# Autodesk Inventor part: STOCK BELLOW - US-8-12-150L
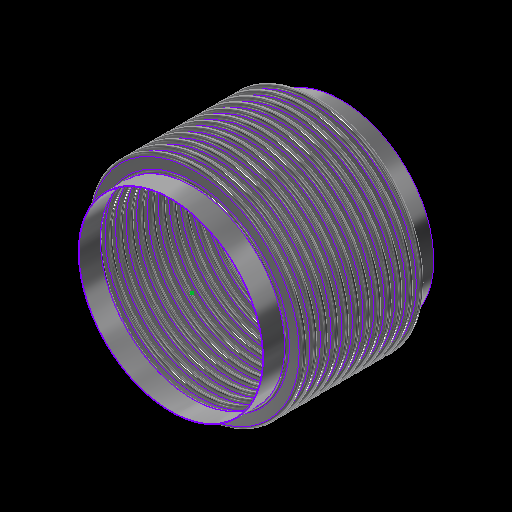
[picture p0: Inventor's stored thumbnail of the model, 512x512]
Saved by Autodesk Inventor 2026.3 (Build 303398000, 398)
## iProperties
Category: 20 GA (0.036 THICK)
RuleStatus: InUse
Created: 2024-01
Part Number: STOCK BELLOW - US-8-12-150L
Project: =STOCK BELLOWS: <Stock Number><SFILL>
Material: ASTM A240-304
Description: =STOCK BELLOWS: <Stock Number>, <SID_> I.D., <SOD_> O.D., <SPLY_> PLY, <Category>, <SNET_CONS> CONS.<PITCH_><STANGENT_> TANGENT<SFILL>
Document SubType Name: Sheet Metal
Designer: GS
Stock Number: U.S-8-12-150L
Surface Area: 8553.82 cm^2
Volume: 389.347 cm^3
Sheet Metal Rule: Default
Appearance: STAINLESS STEEL
Mass: 3137.08 g
Density: 8.05729 g/cm^3
THK: 0.036
ID: 3.500
OD: 4.250
CONS_: 2
PITCH: 0.500
TANGENT: 0.500
BELLOWS_UPSET: 0.000
d79: 1.000
d82: 1.000
d83: 26.000
d84: 24.000
d174: 8
d214: 8
STHK_: 0.036
SID_: 8.625
SOD_: 10.125
SPITCH_: 0.500
STANGENT__: 1.000
SBELLOWS_UPSET_: 0.000
SDIFF_TAN: 1.000
d252: 2
d275: 2
d287: 0.050
d289: 0.500
d290: 0.000
SOD_NECK: 8 11/16
PLY: 1
PSET: 4.178
PBAR: 1.035
COUNTER: 1.500
NET_TUBE: 3.071
CONS: 2
S_CONS: 0
NET_CONS: 2
ID_M: 88.90 mm
OD_M: 107.95 mm
THK_M: 0.91 mm
ID_U: 3.500 in
OD_U: 4.250 in
THK_U: 0.036 in
TANGENT2: 0.500
TAN_TO_TAN: 1.000 in
d80: 2.571
d81: 10
SID: 2.375
SCONS_: 12
SPITCH: 0.250
STANGENT_: 1.000
SBELLOWS_UPSET: 0.000
SNET_CONS: 12
SS_CONS: 0
SCONS: 8
d190: 8
d191: 1
d192: 1
d193: 8
d194: 0
SIZE: 8.00
PRESSURE: 150
d230: 8
STANGENT: 4.000
SPLY_: 1
d233: 8
d234: 0
d263: 2
d265: 1
d268: 2
d269: 0
d286: 2
d288: 1
d291: 2
d292: 0
SREROLL: 0.750
BLETP: 1.000 ul
PRES_Copy: 85
MATTABLE: 20 GA (0.036 THICK)
PART_NUMBER: U.S-8-12-150L
PITCH_: =, <SPITCH_> PITCH,
CFILL: .
SFILL: .
MESH: ,
COMP: 1.22
EXT: 0.61
LAT: 0.26
ANG: 573
ASR: 1601
LSR: 5276
ANSR: 276
PRES: 150
COMPM: 12.2
EXTM: 6.1
LATM: 2.60
ASRM: 280.383
PRESM: 10.342
LSRM: 923.986
ANSRM: 48.336
TEMPMIN: 20
TEMPMAX: 800
TEMPMINM: -7
TEMPMAXM: 427
WEIGHTM: 3.137
WEIGHT: 6.916
Author: GS
Keywords: 20 GA (0.036 THICK)
Comments: =STOCK BELLOW - <STOCK NUMBER>
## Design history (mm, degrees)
sketch "Sketch2"
  geometry: L1 (0, -177.245)-(0, 562.856) reference; L2 (45.364, 0)-(44.45, 0); L3 (48.082, -2.718)-(50.343, -2.718); L4 (48.082, -3.632)-(50.343, -3.632); L5 (50.343, -9.982)-(48.082, -9.982); L6 (50.343, -9.068)-(48.082, -9.068); L7 (45.364, -12.7)-(44.45, -12.7); L8 (48.082, 0)-(48.082, -12.7); L9 (50.343, -6.35)-(53.975, -6.35); L10 (44.45, 0)-(44.45, -12.7); L11 (20.376, 102.841)-(20.376, 101.926); L12 (58.262, 457.127)-(58.262, 349.177); L13 (58.262, 444.427)-(58.262, 336.477); L14 (93.133, -58.817)-(93.133, -71.517); L15 (118.746, -66.401)-(118.746, -66.401); L16 (50.343, -9.068)-(50.343, -9.982); L17 (48.082, -9.068)-(48.082, -9.982); L18 (48.082, -9.525)-(50.343, -9.525); L19 (53.975, 0)-(53.975, -12.7); L20 (-50.343, -9.068)-(-50.343, -9.982); L21 (-50.343, -2.718)-(-48.082, -2.718); L22 (-50.343, -3.632)-(-48.082, -3.632); L23 (-48.082, -9.068)-(-50.343, -9.068); L24 (-50.343, -9.525)-(-48.082, -9.525); L25 (-48.082, -9.982)-(-50.343, -9.982); L26 (-48.082, -9.068)-(-48.082, -9.982); L27 (-44.45, 0.653)-(-44.45, -12.047); L28 (-48.082, -6.35)-(-44.45, -6.35); L29 (-50.343, 0.653)-(-50.343, -12.7); L30 (-53.061, 0)-(-53.975, 0); L31 (-53.975, 0)-(-53.975, -12.7); L32 (-53.061, -12.7)-(-53.975, -12.7); A1 r 2.718 centre (48.082, 0) between (45.364, 0) and (48.082, -2.718); A2 r 3.632 centre (48.082, 0) between (44.45, 0) and (48.082, -3.632); A3 r 3.632 centre (50.343, -6.35) between (50.343, -9.982) and (50.343, -2.718); A4 r 2.718 centre (50.343, -6.35) between (50.343, -9.068) and (50.343, -3.632); A5 r 2.718 centre (48.082, -12.7) between (48.082, -9.982) and (45.364, -12.7); A6 r 3.632 centre (48.082, -12.7) between (48.082, -9.068) and (44.45, -12.7); A7 r 3.175 centre (50.343, -6.35) between (50.343, -9.525) and (53.518, -6.35); A8 r 3.175 centre (48.082, -12.7) between (48.082, -9.525) and (44.907, -12.7); A9 r 2.718 centre (-50.343, -12.7) between (-50.343, -9.982) and (-53.061, -12.7); A10 r 2.718 centre (-48.082, -6.35) between (-48.082, -9.068) and (-48.082, -3.632); A11 r 3.175 centre (-48.082, -6.35) between (-48.082, -9.525) and (-44.907, -6.35); A12 r 3.632 centre (-48.082, -6.35) between (-48.082, -9.982) and (-48.082, -2.718); A13 r 3.175 centre (-50.343, -12.7) between (-50.343, -9.525) and (-53.518, -12.7); A14 r 3.632 centre (-50.343, -12.7) between (-50.343, -9.068) and (-53.975, -12.7); A15 r 2.718 centre (-50.343, 0) between (-53.061, 0) and (-50.343, -2.718); A16 r 3.632 centre (-50.343, 0) between (-53.975, 0) and (-50.343, -3.632); 10 further points
  constraints: 62 end point, 38 point on circle, 20 tangent, 16 centre point, 12 parallel, 9 midpoint, 7 vertical, 6 coincident, 6 concentric, 6 point on line, 4 equal radius, 4 perpendicular, 3 horizontal, 1 collinear, 1 horizontal alignment, 10 other
  dimensions: "THK" = 0.9144 distance of L11.start L11.end; "ID" = 88.9 distance of L11.end point (20.376, 13.026); "OD" = 107.95 distance of L12.start L12.end; "PITCH" = 12.7 distance of L12.start L13.start; "TANGENT" = 12.7 distance of L14.start L14.end; "BELLOWS_UPSET" = 0 distance of L15.start L15.end; "d43" = 88.9 diameter of L10 L1 (= ID); "d44" = 107.95 diameter of L9.end L1 (= OD); "d45" = 0.9144 distance between parallel lines of L5 L6 (computed from THK, PLY); "d46" = 3.6322 radius of A3 (computed from PITCH, THK, PLY); "UPSET_PITCH" = 12.7 distance of L2.end L7.end (derived); "SIDEWALL_ANGLE" = 360 deg dimension on L3 L9 (derived); "CON_GAP" = 5.4356 distance of point (48.082, -9.068) point (48.082, -3.632) (derived); "TAN1" = 4.98728 dimension on A8 (derived); "TAN2" = 4.98728 dimension on A7 (derived); "LEG1" = 2.2606 distance of L18.start L18.end (derived); "d278" = 0.9144 distance between parallel lines of L25 L23 (derived); "d279" = 3.6322 radius of A12 (derived); "d280" = 12.7 distance of L30.end L31.end (derived); "d281" = 360 deg dimension on L21 L28 (derived); "d282" = 5.4356 distance of point (-50.343, -9.068) point (-50.343, -3.632) (derived); "d283" = 4.98728 dimension on A13 (derived); "d284" = 4.98728 dimension on A11 (derived); "d285" = 2.2606 distance of L24.start L24.end (derived); "d293" = 88.9 diameter of L27 L1 (derived); "d294" = 107.95 diameter of L31 L1 (derived)
  node "Sketch Rectangular Pattern1" dims "d31" = 25.4, "ID" = 88.9
  node "Sketch Rectangular Pattern2" dims "d39" = 25.4, "PITCH" = 12.7
revolve "CONS" stored, may be unused: angle "d48" = 90 deg
node "BELLOW MIDPLANE"
pattern_linear "Rectangular Pattern2" dims "d52" = 12.7 (= UPSET_PITCH)
sketch "Sketch5"
  geometry: C1 r 45.364 at (0, 0) reference; C2 r 44.45 at (0, 0) reference
extrude "TANGENT" new body sketch "Sketch5" distance "d53" = 12.7 (= TANGENT); taper "d54" = 0 deg
revolve "SAMETAN" stored, may be unused: angle "d65" = 90 deg
revolve "DIFFTAN" stored, may be unused: angle "d70" = 90 deg
sketch "Sketch9"
  geometry: L1 (53.319, 0)-(-53.319, 0) reference; L2 (0, -17.78)-(0, 17.78) reference; L3 (38.085, 0)-(-38.085, 0); L4 (38.085, -11.906)-(38.085, 11.906); L5 (25.385, -11.906)-(25.385, 11.906); L6 (13.15, 11.906)-(13.15, -11.906); L7 (-25.385, -11.906)-(-25.385, 11.906); L8 (-38.085, -11.906)-(-38.085, 11.906); L9 (37.291, -11.906)-(37.291, 11.906); L10 (38.085, -11.906)-(37.291, -11.906); L11 (38.085, 11.906)-(37.291, 11.906); L12 (13.546, 11.906)-(12.753, 11.906); L13 (12.753, 11.906)-(12.753, -11.906); L14 (12.753, -11.906)-(13.546, -11.906); L15 (13.546, -11.906)-(13.546, 11.906); L16 (-13.546, 11.906)-(-13.546, -11.906); L17 (-13.15, 11.906)-(-13.15, -11.906); L18 (-13.546, -11.906)-(-12.753, -11.906); L19 (-12.753, -11.906)-(-12.753, 11.906); L20 (-12.753, 11.906)-(-13.546, 11.906); L21 (-38.085, -11.906)-(-37.291, -11.906); L22 (-37.291, -11.906)-(-37.291, 11.906); L23 (-37.291, 11.906)-(-38.085, 11.906); L24 (-38.085, 11.906)-(-38.085, -11.906); L25 (38.085, -0.397)-(-38.085, -0.397); L26 (-38.085, -0.397)-(-38.085, 0.397); L27 (-38.085, 0.397)-(38.085, 0.397); L28 (38.085, 0.397)-(38.085, -0.397); L29 (-38.085, 11.906)-(38.085, 11.906); L30 (38.085, 11.906)-(38.085, 12.7); L31 (38.085, 12.7)-(-38.085, 12.7); L32 (-38.085, 12.7)-(-38.085, 11.906); L33 (38.085, -11.906)-(-38.085, -11.906); L34 (-38.085, -11.906)-(-38.085, -12.7); L35 (-38.085, -12.7)-(38.085, -12.7); L36 (38.085, -12.7)-(38.085, -11.906); 30 further points
  constraints: 68 end point, 13 midpoint, 13 parallel, 8 horizontal, 7 perpendicular, 6 equal length, 3 point on line, 2 vertical, 14 other
  dimensions: "d115" = 23.8125 distance of L4.start L4.end (derived); "d116" = 12.7 distance between parallel lines of L4 L5 (derived); "d117" = 12.23516 distance between parallel lines of L5 L6 (derived); "d125" = 38.53427 distance between parallel lines of L7 L6 (derived); "d127" = 12.7 distance between parallel lines of L8 L7 (derived); "d128" = 24.93516 distance between parallel lines of L6 L4 (derived); "d130" = 76.16943 distance between parallel lines of L8 L4 (derived); "RULER_THK" = 0.79375 distance between parallel lines of L4 L9; "d135" = 0.79375 distance of L13.end L14.end (derived); "d138" = 26.29911 distance of L13.end L16.end (derived); "d143" = 0.79375 distance of L22.end L8.end (derived); "d144" = 0.79375 distance between parallel lines of L27 L25 (derived)
extrude "RULER" join sketch "Sketch9" distance "d149" = 0.79375 (derived); taper "d150" = 0 deg
extrude "BARS" join sketch "Sketch9" distance "d151" = 0.79375 (derived); taper "d152" = 0 deg
pattern_linear "Rectangular Pattern4" dims "d155" = 26.29911 (derived)
sketch "Sketch13"
  geometry: L1 (93.149, -52.467)-(93.149, -77.867); L2 (110.452, 0)-(109.537, 0); L3 (110.452, -12.7)-(109.537, -12.7); L4 (124.955, -9.982)-(113.17, -9.982); L5 (124.955, -9.068)-(113.17, -9.068); L6 (124.955, -6.35)-(128.588, -6.35); L7 (113.17, -2.718)-(124.955, -2.718); L8 (113.17, 0)-(113.17, -12.7); L9 (109.537, 0)-(109.537, -12.7); L10 (58.254, -239.256)-(58.254, -496.431); L11 (58.254, -251.956)-(58.254, -509.131); L12 (58.254, -277.356)-(58.254, -534.531); L13 (58.254, -290.056)-(58.254, -547.231); L14 (58.254, -302.756)-(58.254, -559.931); L15 (58.254, -315.456)-(58.254, -572.631); L16 (58.254, -328.156)-(58.254, -585.331); L17 (58.254, -264.656)-(58.254, -521.831); L18 (20.376, 102.841)-(20.376, 101.926); L19 (113.17, -3.632)-(124.955, -3.632); L20 (0, -722.965)-(0, 240.475) reference; L21 (-25.718, 0)-(154.305, 0) reference; A1 r 2.718 centre (113.17, 0) between (110.452, 0) and (113.17, -2.718); A2 r 2.718 centre (113.17, -12.7) between (113.17, -9.982) and (110.452, -12.7); A3 r 3.632 centre (113.17, -12.7) between (113.17, -9.068) and (109.537, -12.7); A4 r 2.718 centre (124.955, -6.35) between (124.955, -9.068) and (124.955, -3.632); A5 r 3.632 centre (124.955, -6.35) between (124.955, -9.982) and (124.955, -2.718); A6 r 3.632 centre (113.17, 0) between (109.537, 0) and (113.17, -3.632); 6 further points; 1 other entity
  constraints: 38 end point, 15 point on circle, 9 tangent, 6 centre point, 6 parallel, 5 vertical alignment, 4 point on line, 4 vertical, 3 coincident, 3 concentric, 2 collinear, 2 equal radius, 1 horizontal, 1 perpendicular, 23 other
  dimensions: "SBELLOWS_UPSET_" = 0 distance of point (118.762, -66.401) point (118.762, -66.401); "STOTAL_THK_BELLOW__" = 0.9144 distance between parallel lines of L4 L5 (derived); "d224" = 3.6322 radius of A5 (derived); "d225" = 12.7 distance of L2.end L3.end (derived); "SSIDEWALL_ANGLE_" = 360 deg dimension on L7 L6 (derived); "SSCON_GAP_" = 5.4356 distance of point (113.17, -9.068) point (113.17, -3.632) (derived); "d235" = 219.075 diameter of L9 L20 (derived); "d236" = 257.175 diameter of L6.end L20 (derived)
  node "Sketch Rectangular Pattern4" dims "d228" = 25.4
  node "Sketch Rectangular Pattern5" dims "d229" = 25.4
revolve "SBELLOW" stored, may be unused: angle "d197" = 90 deg
pattern_linear "Rectangular Pattern5" dims "d204" = 12.7 (derived)
revolve "STANGENT" stored, may be unused: angle "d240" = 90 deg
revolve "SSAMETAN" stored, may be unused: angle "d241" = 90 deg
revolve "SDIFFTAN" stored, may be unused: angle "d246" = 90 deg
revolve "INVCON" stored, may be unused: angle "d295" = 90 deg
pattern_linear "Rectangular Pattern6" dims "d298" = 12.7 (derived)
revolve "INVTANGENT" stored, may be unused: angle "d302" = 90 deg
revolve "INVSAMETAN" stored, may be unused: angle "d307" = 90 deg
revolve "INVDIFFTAN" stored, may be unused: angle "d312" = 90 deg
sketch "ID BELLOW MOUNT CALC"
  geometry: L1 (44.45, 0)-(38.1, 0); L2 (38.1, 0)-(38.1, 12.7); L3 (38.1, 12.7)-(44.45, 12.7); L4 (44.45, 12.7)-(44.45, 0); L5 (36.513, 12.7)-(35.598, 12.7); L6 (35.598, 12.7)-(35.598, 0); L7 (35.598, 0)-(36.513, 0); L8 (36.513, 0)-(36.513, 12.7); L9 (0, -2.54)-(0, 15.24) reference; L10 (-8.89, 0)-(53.34, 0) reference; 1 further point
  constraints: 16 end point, 5 parallel, 2 collinear, 2 horizontal, 2 perpendicular
  dimensions: "d314" = 12.7 distance of L5.end L6.end (derived); "d315" = 0.9144 distance of L5.start L5.end (derived); "IG" = 1.5875 distance between parallel lines of L2 L8; "PIPE_OD" = 88.9 diameter of L4 L9; "PIPE_WALL" = 6.35 distance of L2.end L3.end; "ID_MT_BELLOW" = 71.1962 diameter of L6 L9 (derived)
revolve "CFILL" stored, may be unused: angle "d320" = 90 deg
pattern_linear "Rectangular Pattern7" dims "d323" = 12.7 (derived)
revolve "SFILL" stored, may be unused: angle "d324" = 90 deg
pattern_linear "Rectangular Pattern8" dims "d327" = 12.7 (derived)
node "STOCK BELLOW MIDPLANE"
node "BELLOW"
sketch "Sketch6"
  geometry: L1 (-12.7, 45.364)-(0, 45.364); L2 (0, 45.364)-(0, 44.45); L3 (0, 44.45)-(-12.7, 44.45); L4 (-12.7, 44.45)-(-12.7, 45.364); L5 (10.16, 0)-(-60.96, 0) reference; L6 (-38.1, -89.422)-(-38.1, 153.44) reference; 1 further point
  constraints: 8 end point, 2 parallel, 1 horizontal, 1 perpendicular
  dimensions: "d61" = 12.7 distance of L2.end L3.end (derived); "d62" = 0.9144 distance of L1.end L2.end (derived); "d63" = 88.9 diameter of L3 L5 (derived); "d64" = 25.4 distance between parallel lines of L4 L6 (derived)
sketch "Sketch12"
  geometry: 1 further point
sketch "Sketch14"
  geometry: L1 (-25.4, 110.452)-(0, 110.452); L2 (0, 110.452)-(0, 109.537); L3 (0, 109.537)-(-25.4, 109.537); L4 (-25.4, 109.537)-(-25.4, 110.452); L5 (5.08, 0)-(-30.48, 0) reference; L6 (0, -22.09)-(0, 132.542) reference; 1 further point
  constraints: 8 end point, 2 parallel, 1 collinear, 1 horizontal, 1 perpendicular
  dimensions: "d237" = 0.9144 distance of L3.end L1.start (derived); "d238" = 219.075 diameter of L3 L5 (derived); "d239" = 25.4 distance of L1.start L1.end (derived); "SOD_NECK" = 220.9038 diameter of L1 L5 (derived)
sketch "Sketch15"
  geometry: L1 (-22.09, 0)-(132.542, 0) reference; L2 (109.538, -152.4)-(110.452, -152.4); L3 (110.452, -152.4)-(110.452, -177.8); L4 (110.452, -177.8)-(109.538, -177.8); L5 (109.538, -177.8)-(109.538, -152.4); L6 (0, -215.9)-(0, 50.8) reference; 1 further point
  constraints: 8 end point, 2 parallel, 1 horizontal, 1 perpendicular
  dimensions: "d205" = 25.4 distance of L4.end L2.start (derived); "d206" = 0.9144 distance of L3.end L4.end (derived); "d207" = 219.075 diameter of L5 L6 (derived); "d208" = 152.4 distance between parallel lines of L1 L2 (derived)
node "TANGENT_"
node "SAME_TAN"
sketch "Sketch8"
  geometry: L1 (45.364, -25.4)-(44.45, -25.4); L2 (44.45, -25.4)-(44.45, -38.1); L3 (44.45, -38.1)-(45.364, -38.1); L4 (45.364, -38.1)-(45.364, -25.4); L5 (0, -48.26)-(0, 22.86) reference; L6 (-89.422, 0)-(153.44, 0) reference; 1 further point
  constraints: 8 end point, 2 parallel, 1 horizontal, 1 perpendicular
  dimensions: "d66" = 88.9 diameter of L2 L5 (derived); "TOTAL_THK_BELLOW" = 0.9144 distance of L2.end L3.end (derived); "d68" = 25.4 distance between parallel lines of L1 L6 (derived); "d69" = 12.7 distance of L1.end L2.end (derived)
node "DIFF_TAN"
node "Sketch Rectangular Pattern3" dims "d138" = 26.29911 (derived), "d141" = 25.4
node "SBELLOW_"
node "STANGENT_"
node "SSAME_TAN"
sketch "Sketch16"
  geometry: L1 (110.452, -152.4)-(109.538, -152.4); L2 (109.538, -152.4)-(109.538, -177.8); L3 (109.538, -177.8)-(110.452, -177.8); L4 (110.452, -177.8)-(110.452, -152.4); L5 (0, -215.9)-(0, 50.8) reference; L6 (-22.09, 0)-(132.542, 0) reference; 1 further point
  constraints: 8 end point, 2 parallel, 1 horizontal, 1 perpendicular
  dimensions: "SDIFF_TAN" = 25.4 distance of L3.end L1.start; "d243" = 0.9144 distance of L2.end L3.end (derived); "d244" = 152.4 distance between parallel lines of L1 L6 (derived); "d245" = 219.075 diameter of L2 L5 (derived)
node "SDIFF_TAN"
body "Solid15"
sketch "Sketch17"
  geometry: L1 (53.975, 12.7)-(53.061, 12.7); L2 (53.061, 12.7)-(53.061, 0); L3 (53.061, 0)-(53.975, 0); L4 (53.975, 0)-(53.975, 12.7); L5 (0, -2.54)-(0, 15.24) reference; L6 (-10.795, 0)-(64.77, 0) reference; 2 further points
  constraints: 8 end point, 2 parallel, 1 horizontal, 1 midpoint, 1 perpendicular, 1 point on line
  dimensions: "INVTANGENT" = 12.7 distance of L3.end L1.start (derived); "d300" = 0.9144 distance of L1.start L1.end (derived); "d301" = 107.95 diameter of L4 L5 (derived)
body "Solid16"
sketch "Sketch18"
  geometry: L1 (53.975, -25.4)-(53.061, -25.4); L2 (53.061, -25.4)-(53.061, -38.1); L3 (53.061, -38.1)-(53.975, -38.1); L4 (53.975, -38.1)-(53.975, -25.4); L5 (-10.795, 0)-(64.77, 0) reference; L6 (0, -48.26)-(0, 22.86) reference; 1 further point
  constraints: 8 end point, 2 parallel, 1 horizontal, 1 perpendicular
  dimensions: "d303" = 25.4 distance between parallel lines of L1 L5 (derived); "d304" = 12.7 distance of L3.end L1.start (derived); "d305" = 0.9144 distance of L2.end L3.end (derived); "d306" = 107.95 diameter of L4 L6 (derived)
body "Solid17"
sketch "Sketch19"
  geometry: L1 (53.975, -25.4)-(53.061, -25.4); L2 (53.061, -25.4)-(53.061, -38.1); L3 (53.061, -38.1)-(53.975, -38.1); L4 (53.975, -38.1)-(53.975, -25.4); L5 (0, -48.26)-(0, 22.86) reference; L6 (-10.795, 0)-(64.77, 0) reference; 1 further point
  constraints: 8 end point, 2 parallel, 1 horizontal, 1 perpendicular
  dimensions: "d308" = 12.7 distance of L1.end L2.end (derived); "d309" = 107.95 diameter of L4 L5 (derived); "d310" = 0.9144 distance of L2.end L3.end (derived); "d311" = 25.4 distance between parallel lines of L1 L6 (derived)
body "Solid18"
body "Solid19"
body "Solid20"
other parameters: "BMPL" = -76.2, "PSET" = 106.1212 (computed from OD, THK, PLY) [user parameter], "PBAR" = 26.29911 (= 0.570796 x PITCH + OD - ID) [user parameter; used in 1 equation term], "COUNTER" = 15 [user parameter], "NET_TUBE" = 77.99823 (computed from CONS_, PBAR, TANGENT) [user parameter], "S_CONS" = 0 [user parameter; used in 1 equation term], "ID_M" = 88.9 (= ID) [user parameter], "OD_M" = 107.95 (= OD) [user parameter], "THK_M" = 0.9144 (= THK) [user parameter], "ID_U" = 88.9 (= ID) [user parameter], "OD_U" = 107.95 (= OD) [user parameter], "THK_U" = 0.9144 (= THK) [user parameter], "D_UNITS" = 0 [user parameter], "TANGENT2" = 12.7 [user parameter], "TAN_TO_TAN" = 25.4 [user parameter], "OD_NECK" = 90.7288 [user parameter], "d79" = 25.4, "d80" = 65.29823 [user parameter], "d82" = 25.4, "d83" = 660.4, "d84" = 609.6, "sa_0" = 4, "FRAME_THK" = 0.79375 [user parameter], "CON_FLAT" = 12.23516 [user parameter], "SID" = 60.325 [user parameter], "SPITCH" = 6.35 [user parameter], "STANGENT_" = 25.4 [user parameter], "SBELLOWS_UPSET" = 0 [user parameter], "SS_CONS" = 0 [user parameter], "STAN_TO_TAN_" = 152.4 [user parameter], "d100" = 0.9144 [user parameter], "d191" = 25.4 [user parameter], "d194" = 0 [user parameter], "STANGENT" = 101.6 [user parameter], "d234" = 0 [user parameter], "SUPSET_PITCH_" = 12.7 [user parameter], "d269" = 0 [user parameter], "d287" = 1.27, "d289" = 12.7, "d290" = 0, "d292" = 0 [user parameter], "Thickness" = 3.048 (derived), "KFactor" = 4.4, "BendRadius" = 3.048 (derived), "BendReliefWidth" = 3.048 (derived), "BendReliefDepth" = 1.524 (derived), "CornerReliefSize" = 12.192 (derived), "SeamGap" = 0.00508, "MinimumRemnant" = 6.096 (derived), "TransitionRadius" = 3.048 (derived), "JacobiRadiusSize" = 3.048 (derived), "GapSize" = 3.048 (derived), "SREROLL" = 19.05 [user parameter], "CUR_STK_PITCH" = 12.7 [user parameter], "d328" = -76.2 (derived), "ASR" = 16010 [user parameter], "LSR" = 52760 [user parameter], "BLETP" = 1 [user parameter], "ASRM" = 2803.8313 [user parameter], "PRESM" = 103.41975 [user parameter], "LSRM" = 9239.8588 [user parameter], "ANSRM" = 483.3588 [user parameter], "TEMPMIN" = 2664.83333 [user parameter], "TEMPMAX" = 6998.16667 [user parameter], "TEMPMINM" = 2664.83333 [user parameter], "TEMPMAXM" = 6998.16667 [user parameter], "WEIGHT" = 31.3708 [user parameter], "WEIGHTM" = 0.03137 [user parameter]
